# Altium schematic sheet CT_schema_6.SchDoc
size 521 x 498 mm
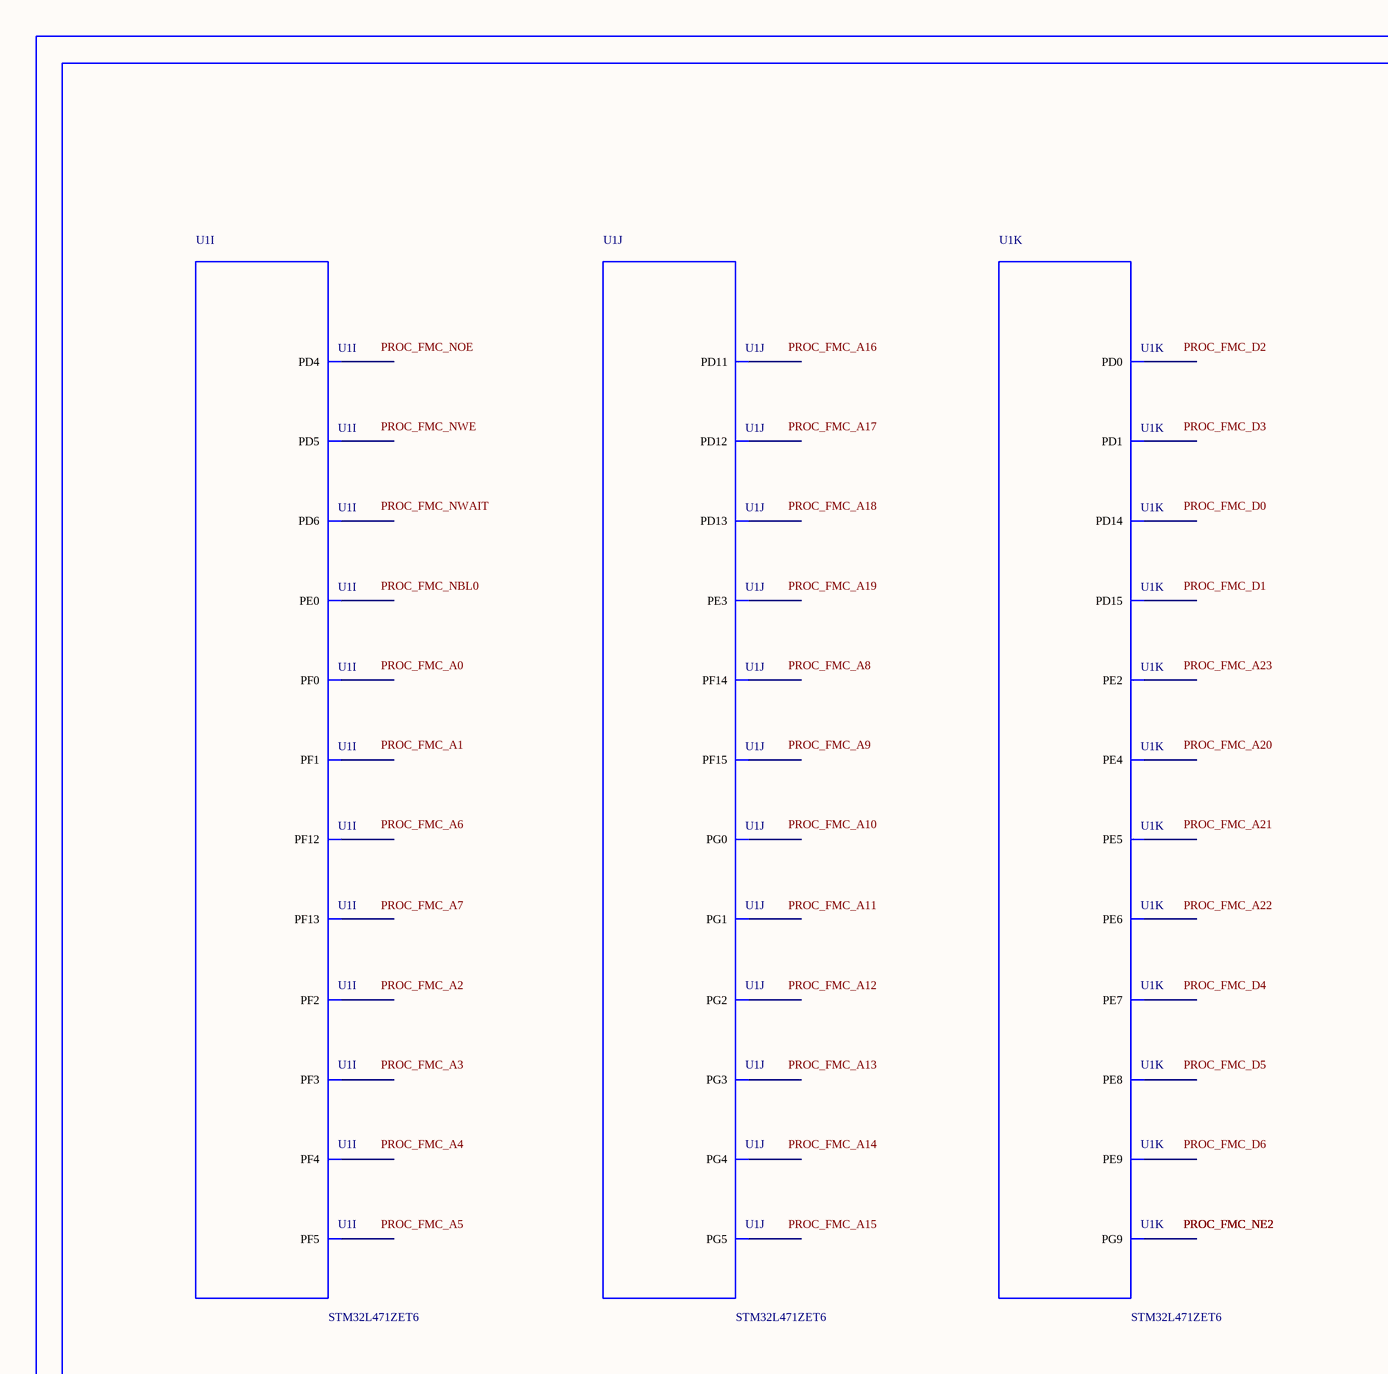
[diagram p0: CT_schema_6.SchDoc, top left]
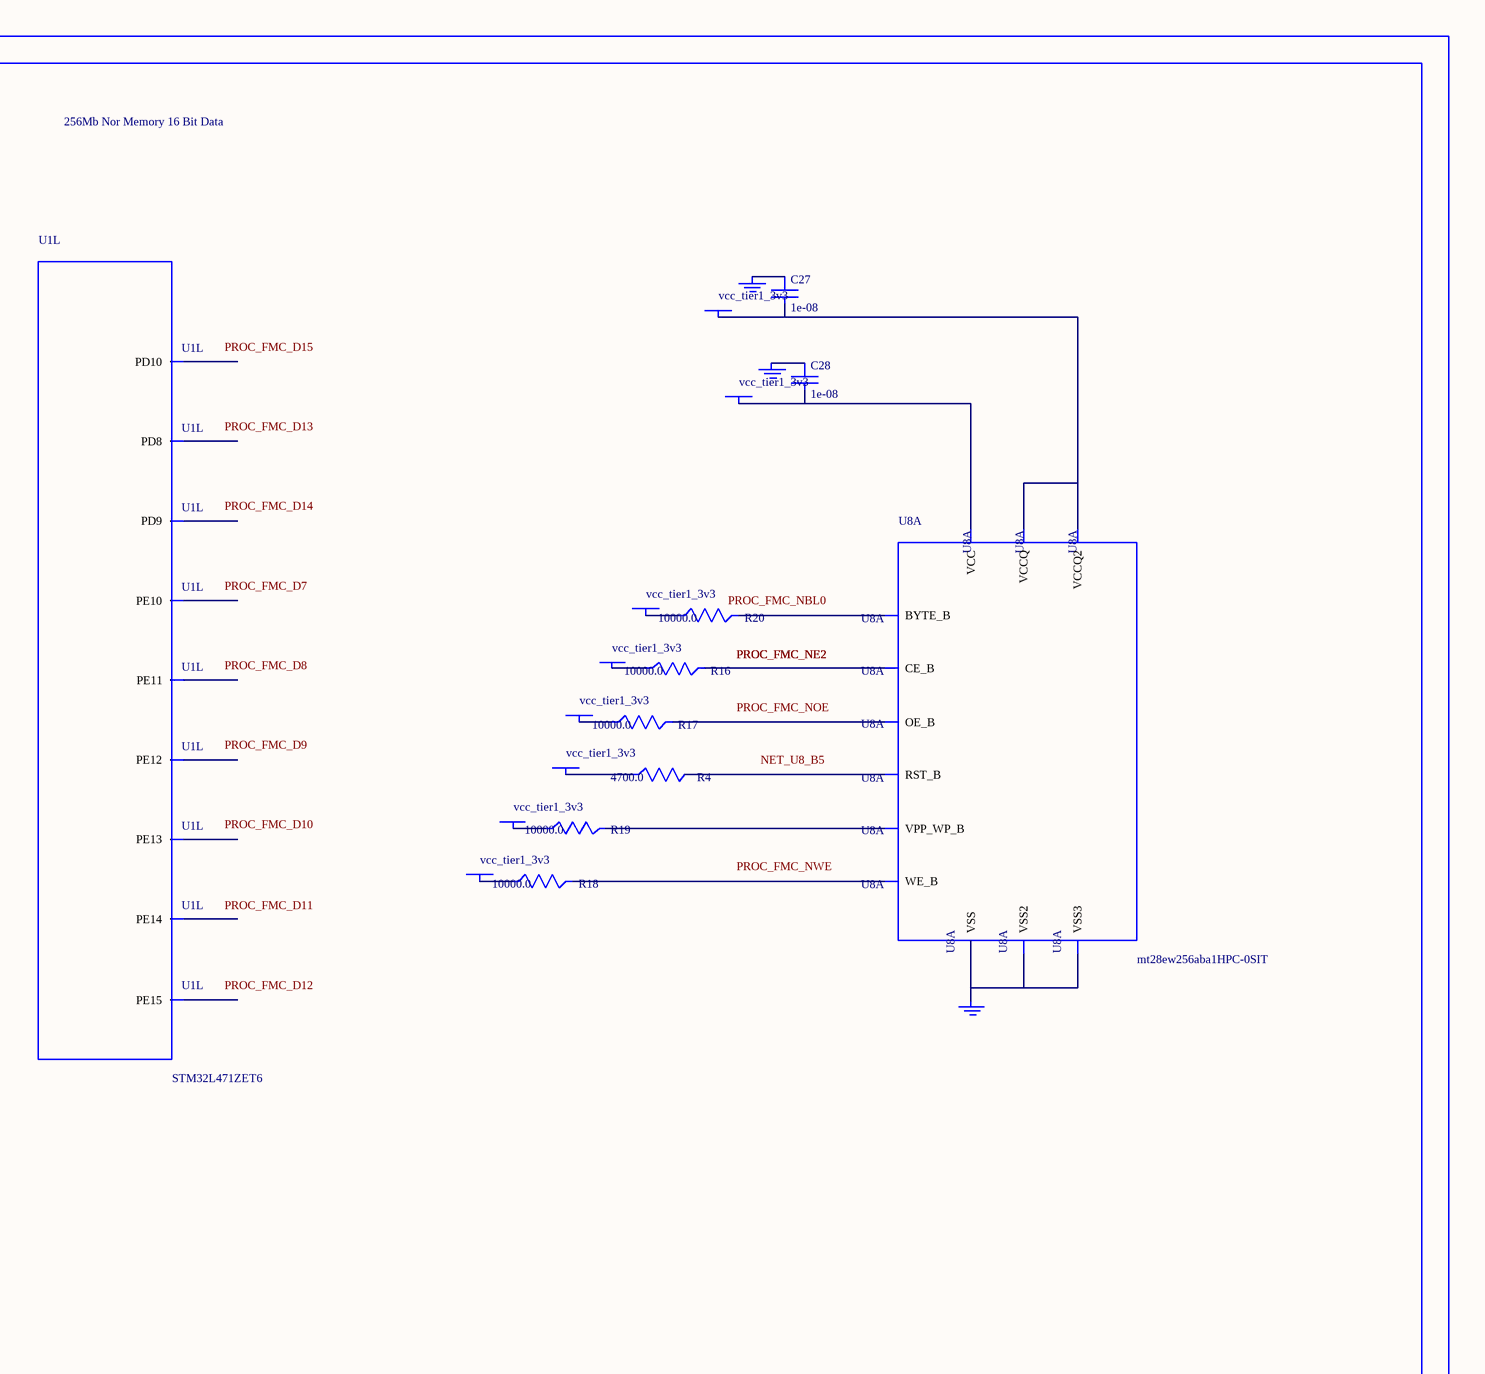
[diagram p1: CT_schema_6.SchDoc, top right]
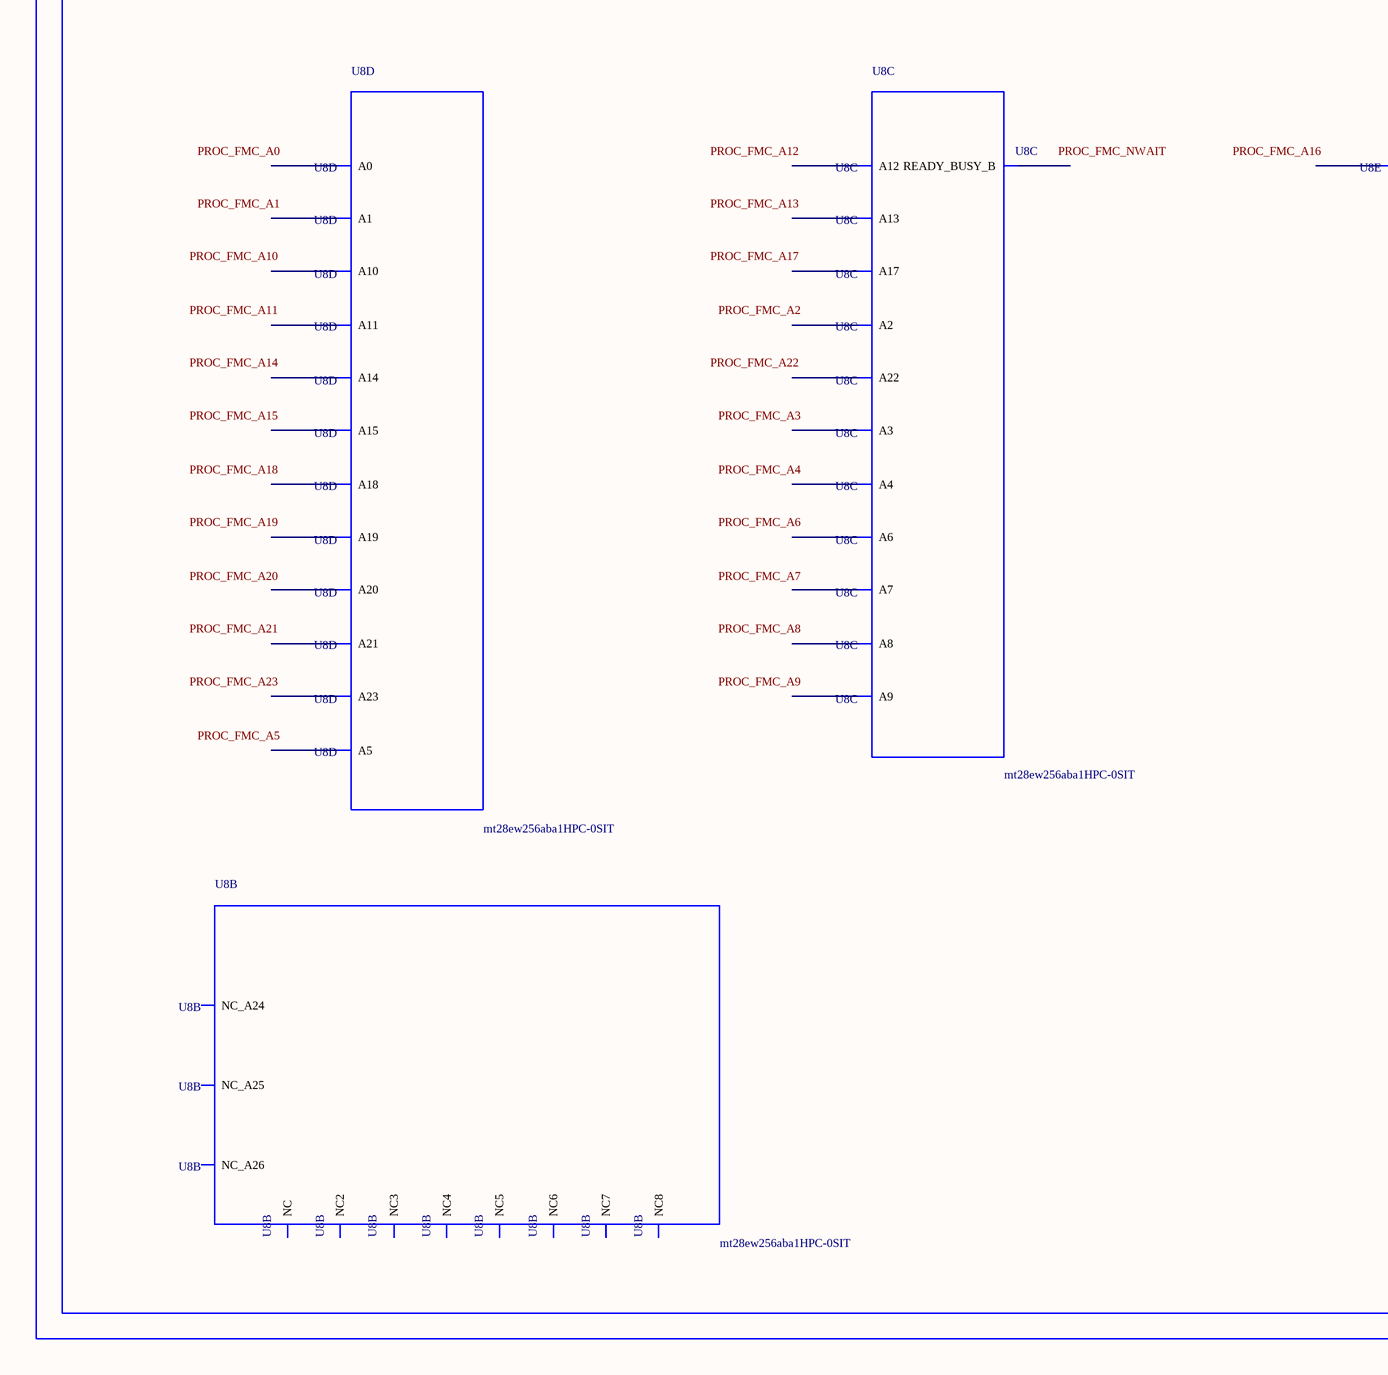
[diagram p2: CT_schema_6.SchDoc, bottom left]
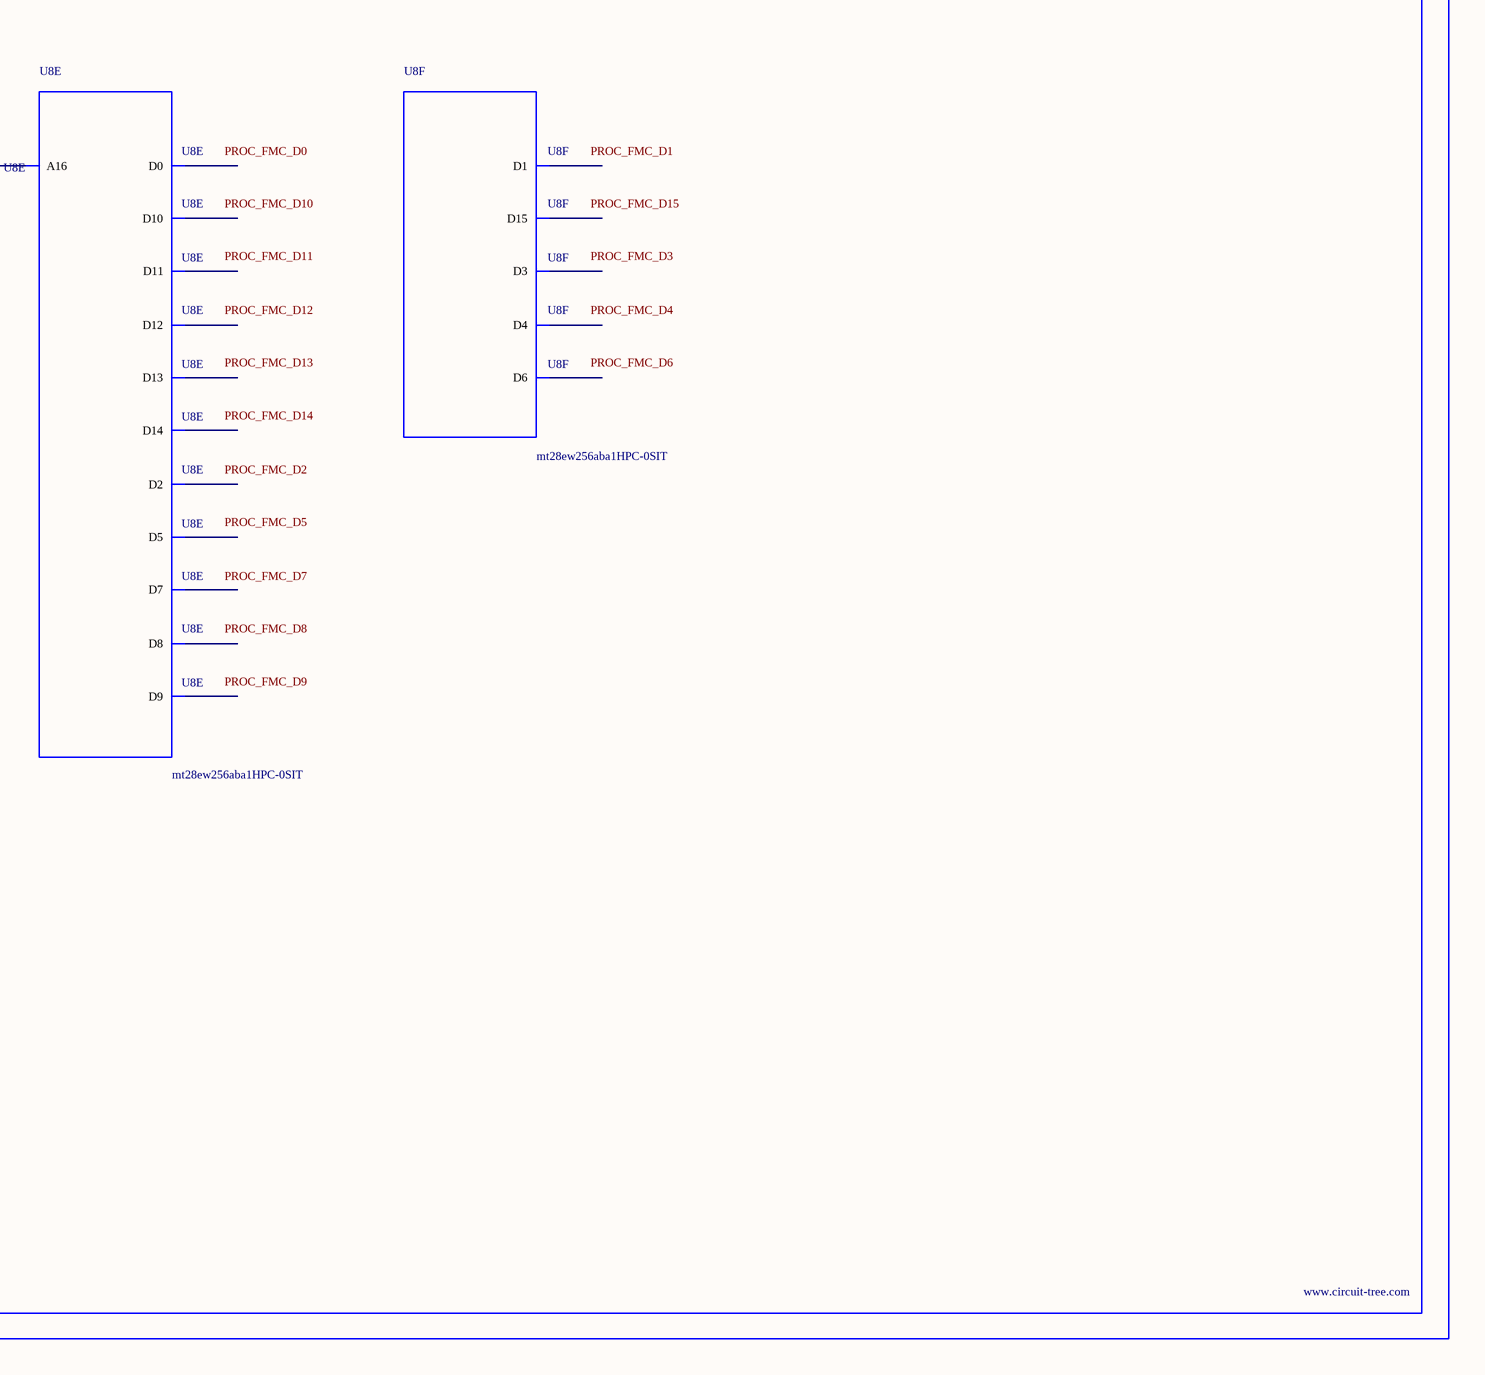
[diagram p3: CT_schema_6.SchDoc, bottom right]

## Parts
BORDER5  (no value)
C27  1e-08  [C0402]
C28  1e-08  [C0402]
GND_INSTANCE_5_0  (no value)
GND_INSTANCE_5_1  (no value)
GND_INSTANCE_5_2  (no value)
POWER_INSTANCE_5_0  vcc_tier1_3v3
POWER_INSTANCE_5_1  vcc_tier1_3v3
POWER_INSTANCE_5_2  vcc_tier1_3v3
POWER_INSTANCE_5_3  vcc_tier1_3v3
POWER_INSTANCE_5_4  vcc_tier1_3v3
POWER_INSTANCE_5_5  vcc_tier1_3v3
POWER_INSTANCE_5_6  vcc_tier1_3v3
POWER_INSTANCE_5_7  vcc_tier1_3v3
R4  4700.0  [R0603]
R16  10000.0  [R0603]
R17  10000.0  [R0603]
R18  10000.0  [R0603]
R19  10000.0  [R0603]
R20  10000.0  [R0603]
U1  STM32L471ZET6  [LQFP144]  (parts I,J,K,L of 13)
U8  mt28ew256aba1HPC-0SIT  [LBGA-64]  (parts A,B,C,D,E,F of 6)

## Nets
NetC27_1: C27.1 GND_INSTANCE_5_0.0(GND)
NetC27_2: C27.2 POWER_INSTANCE_5_0.0(PWR) U8.D8(VCCQ) U8.F1(VCCQ2)
NetC28_1: C28.1 GND_INSTANCE_5_1.0(GND)
NetC28_2: C28.2 POWER_INSTANCE_5_1.0(PWR) U8.G5(VCC)
NetGND_INSTANCE_5_2_0: GND_INSTANCE_5_2.0(GND) U8.E8(VSS) U8.H2(VSS2) U8.H7(VSS3)
NetPOWER_INSTANCE_5_2_0: POWER_INSTANCE_5_2.0(PWR) R16.1
NetPOWER_INSTANCE_5_3_0: POWER_INSTANCE_5_3.0(PWR) R17.1
NetPOWER_INSTANCE_5_4_0: POWER_INSTANCE_5_4.0(PWR) R18.1
NetPOWER_INSTANCE_5_5_0: POWER_INSTANCE_5_5.0(PWR) R19.1
NetPOWER_INSTANCE_5_6_0: POWER_INSTANCE_5_6.0(PWR) R20.1
NetPOWER_INSTANCE_5_7_0: POWER_INSTANCE_5_7.0(PWR) R4.1
NetR4_2: R4.2 U8.B5(RST_B)
NetR16_2: R16.2 U8.F2(CE_B)
NetR17_2: R17.2 U8.G2(OE_B)
NetR18_2: R18.2 U8.A5(WE_B)
NetR19_2: R19.2 U8.B4(VPP_WP_B)
NetR20_2: R20.2 U8.F7(BYTE_B)

Not connected (* = marked no-connect by the designer): U1 1(PE2) 2(PE3) 3(PE4) 4(PE5) 5(PE6) 10(PF0) 11(PF1) 12(PF2) 13(PF3) 14(PF4) 15(PF5) 50(PF12) 53(PF13) 54(PF14) 55(PF15) 56(PG0) 57(PG1) 58(PE7) 59(PE8) 60(PE9) 63(PE10) 64(PE11) 65(PE12) 66(PE13) 67(PE14) 68(PE15) 77(PD8) 78(PD9) 79(PD10) 80(PD11) 81(PD12) 82(PD13) 85(PD14) 86(PD15) 87(PG2) 88(PG3) 89(PG4) 90(PG5) 114(PD0) 115(PD1) 118(PD4) 119(PD5) 122(PD6) 124(PG9) 141(PE0); U8 A1(NC) A2(A3) A3(A7) A4(READY_BUSY_B) A6(A9) A7(A13) A8(NC2) B1(NC_A26) B2(A4) B3(A17) B6(A8) B7(A12) B8(A22) C1(NC3) C2(A2) C3(A6) C4(A18) C5(A21) C6(A10) C7(A14) C8(A23) D1(NC4) D2(A1) D3(A5) D4(A20) D5(A19) D6(A11) D7(A15) E1(NC5) E2(A0) E3(D0) E4(D2) E5(D5) E6(D7) E7(A16) F3(D8) F4(D10) F5(D12) F6(D14) F8(NC_A24) G1(NC6) G3(D9) G4(D11) G6(D13) G7(D15) G8(NC_A25) H1(NC7) H3(D1) H4(D3) H5(D4) H6(D6) H8(NC8)

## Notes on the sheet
- Labels drawn without touching a wire or pin: NET_U8_B5, PROC_FMC_A0, PROC_FMC_A1, PROC_FMC_A2, PROC_FMC_A3, PROC_FMC_A4, PROC_FMC_A5, PROC_FMC_A6, PROC_FMC_A7, PROC_FMC_A8, PROC_FMC_A9, PROC_FMC_A10, PROC_FMC_A11, PROC_FMC_A12, PROC_FMC_A13, PROC_FMC_A14, PROC_FMC_A15, PROC_FMC_A16, PROC_FMC_A17, PROC_FMC_A18, PROC_FMC_A19, PROC_FMC_A20, PROC_FMC_A21, PROC_FMC_A22, PROC_FMC_A23, PROC_FMC_D0, PROC_FMC_D1, PROC_FMC_D2, PROC_FMC_D3, PROC_FMC_D4, PROC_FMC_D5, PROC_FMC_D6, PROC_FMC_D7, PROC_FMC_D8, PROC_FMC_D9, PROC_FMC_D10, PROC_FMC_D11, PROC_FMC_D12, PROC_FMC_D13, PROC_FMC_D14, PROC_FMC_D15, PROC_FMC_NBL0, PROC_FMC_NOE, PROC_FMC_NWAIT, PROC_FMC_NWE

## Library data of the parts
BORDER5 = BORDER_PAGE5
C27 C28 = C0402C103K3RAC
GND_INSTANCE_5_0-GND_INSTANCE_5_2 = GND
POWER_INSTANCE_5_0-POWER_INSTANCE_5_7 = PWR
R4 = RC0603JR-074K7L
R16-R20 = RC0603JR-0710KL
